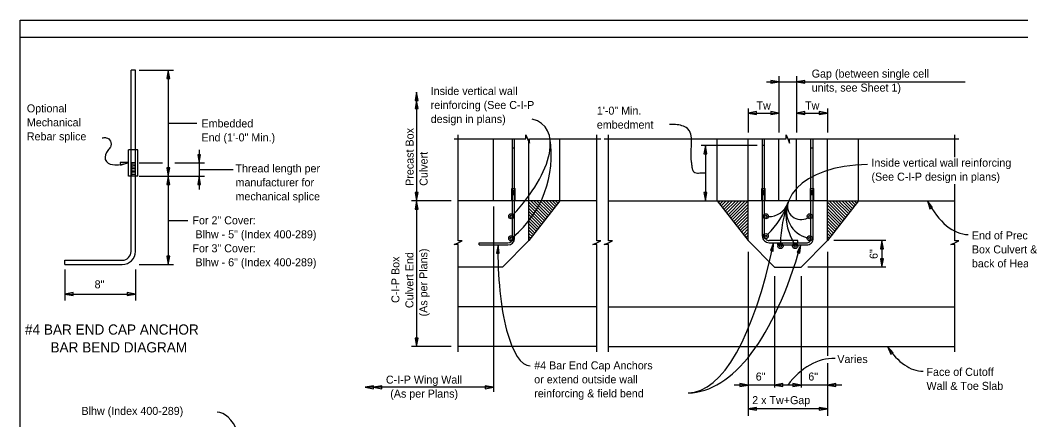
# Model space of a CAD drawing. Extents: x 0 to 30.8, y 0 to 19.8.
# Drawn here: x 0 to 18.91, y 12.25 to 19.8 of the extents above; entities that cross this region are included whole.
import ezdxf

# ---------------------------------------------------------------- set-up
doc = ezdxf.new("R2010")
doc.units = 0
for name, color, linetype in [('Dimension', 7, 'Continuous'), ('Leader', 7, 'Continuous'), ('Miscellaneous', 7, 'Continuous'), ('Miscellaneous1', 7, 'Continuous'), ('Rebar', 7, 'Continuous'), ('SubStrConc', 7, 'Continuous'), ('SubStrConc_h', 7, 'Continuous'), ('TextStructures', 7, 'Continuous')]:
    doc.layers.add(name, color=color, linetype=linetype)

msp = doc.modelspace()

# ---------------------------------------------------------------- linework, layer by layer
at = {"layer": 'Dimension'}
for p, q in [((2.253, 18.853), (2.902, 18.853)), ((2.8, 18.853), (2.8, 16.853)), ((14.335, 18.743), (14.335, 17.678)), ((14.668, 18.743), (14.668, 17.678)), ((14.098, 18.633), (14.335, 18.633)), ((14.335, 18.633), (14.668, 18.633)), ((14.668, 18.633), (17.851, 18.633)), ((7.491, 18.44), (7.491, 16.39)), ((13.751, 18.129), (13.751, 17.678)), ((13.751, 18.045), (14.335, 18.045)), ((14.668, 18.045), (15.251, 18.045)), ((15.251, 18.129), (15.251, 17.678)), ((2.8, 17.853), (3.337, 17.853)), ((17.656, 17.21), (17.656, 17.634)), ((13.922, 17.431), (12.868, 17.431)), ((12.944, 17.431), (12.944, 16.39)), ((3.383, 17.353), (3.383, 17.103)), ((2.253, 17.103), (2.688, 17.103)), ((2.923, 17.103), (3.483, 17.103)), ((3.383, 17.103), (3.383, 16.853)), ((2.253, 16.853), (3.483, 16.853)), ((2.8, 16.853), (2.8, 15.187)), ((3.383, 16.978), (4.023, 16.978)), ((3.383, 16.853), (3.383, 16.603)), ((8.145, 16.39), (7.393, 16.39)), ((7.491, 16.39), (7.491, 13.64)), ((8.945, 16.284), (8.945, 12.783)), ((2.8, 16.02), (3.172, 16.02)), ((16.351, 15.64), (15.374, 15.64)), ((16.28, 15.64), (16.28, 15.14)), ((13.751, 15.425), (13.751, 12.335)), ((15.251, 15.425), (15.251, 13.464)), ((2.253, 15.187), (2.902, 15.187)), ((16.351, 15.14), (14.882, 15.14)), ((0.847, 15.091), (0.847, 14.508)), ((2.18, 15.091), (2.18, 14.508)), ((14.251, 14.966), (14.251, 12.869)), ((14.751, 14.966), (14.751, 12.869)), ((0.847, 14.63), (2.18, 14.63)), ((8.145, 13.64), (7.393, 13.64)), ((15.251, 13.329), (15.251, 12.335)), ((8.943, 12.872), (6.52, 12.872)), ((13.751, 12.913), (13.488, 12.913)), ((14.251, 12.913), (13.751, 12.913)), ((14.751, 12.913), (14.251, 12.913)), ((15.251, 12.913), (14.751, 12.913)), ((15.525, 12.913), (15.251, 12.913)), ((15.251, 12.465), (13.751, 12.465))]:
    msp.add_line(p, q, dxfattribs=at)
for points in [[(2.8, 18.853), (2.774, 18.697), (2.827, 18.697)], [(14.335, 18.633), (14.179, 18.66), (14.179, 18.607)], [(14.668, 18.633), (14.824, 18.607), (14.824, 18.66)], [(7.491, 18.44), (7.465, 18.284), (7.517, 18.284)], [(7.491, 18.284), (7.465, 18.128), (7.517, 18.128)], [(13.751, 18.045), (13.908, 18.019), (13.908, 18.072)], [(14.335, 18.045), (14.179, 18.072), (14.179, 18.019)], [(14.668, 18.045), (14.824, 18.019), (14.824, 18.072)], [(15.251, 18.045), (15.095, 18.072), (15.095, 18.019)], [(12.944, 17.431), (12.918, 17.275), (12.971, 17.275)], [(3.383, 17.103), (3.409, 17.26), (3.356, 17.26)], [(2.05, 17.11), (1.892, 17.111), (1.9, 17.059)], [(2.8, 16.853), (2.827, 17.01), (2.774, 17.01)], [(2.8, 16.853), (2.774, 16.697), (2.827, 16.697)], [(3.383, 16.853), (3.356, 16.697), (3.409, 16.697)], [(7.491, 16.39), (7.517, 16.546), (7.465, 16.546)], [(12.944, 16.39), (12.971, 16.546), (12.918, 16.546)], [(7.491, 16.39), (7.465, 16.233), (7.517, 16.233)], [(17.137, 16.39), (17.187, 16.239), (17.234, 16.264)], [(9.029, 15.556), (9, 15.401), (9.053, 15.4)], [(14.234, 15.598), (14.176, 15.45), (14.228, 15.44)], [(14.747, 15.556), (14.679, 15.413), (14.73, 15.399)], [(16.28, 15.64), (16.253, 15.483), (16.306, 15.483)], [(2.8, 15.187), (2.827, 15.343), (2.774, 15.343)], [(16.28, 15.14), (16.306, 15.296), (16.253, 15.296)], [(0.847, 14.63), (1.003, 14.604), (1.003, 14.657)], [(2.18, 14.63), (2.024, 14.657), (2.024, 14.604)], [(7.491, 13.64), (7.517, 13.796), (7.465, 13.796)], [(16.384, 13.64), (16.448, 13.495), (16.492, 13.524)], [(6.52, 12.872), (6.676, 12.845), (6.676, 12.898)], [(6.676, 12.872), (6.832, 12.845), (6.832, 12.898)], [(8.943, 12.872), (8.787, 12.898), (8.787, 12.845)], [(13.751, 12.913), (13.595, 12.94), (13.595, 12.887)], [(14.251, 12.913), (14.408, 12.887), (14.408, 12.94)], [(14.751, 12.913), (14.595, 12.94), (14.595, 12.887)], [(15.251, 12.913), (15.408, 12.887), (15.408, 12.94)], [(13.751, 12.465), (13.908, 12.438), (13.908, 12.491)], [(15.251, 12.465), (15.095, 12.491), (15.095, 12.438)]]:
    msp.add_lwpolyline(points, close=True, dxfattribs=at)
for points in [[(8.276, 13.54), (8.276, 15.564), (8.198, 15.564), (8.276, 15.598), (8.353, 15.632), (8.276, 15.632), (8.276, 17.634)], [(8.198, 17.556), (9.552, 17.556), (9.552, 17.634), (9.586, 17.556), (9.62, 17.479), (9.62, 17.556), (10.973, 17.556)], [(10.896, 13.54), (10.896, 15.564), (10.818, 15.564), (10.896, 15.598), (10.973, 15.632), (10.896, 15.632), (10.896, 17.634)], [(11.035, 17.556), (14.468, 17.556), (14.468, 17.634), (14.501, 17.556), (14.535, 17.479), (14.535, 17.556), (17.734, 17.556)], [(11.112, 13.54), (11.112, 15.564), (11.035, 15.564), (11.112, 15.598), (11.19, 15.632), (11.112, 15.632), (11.112, 17.634)], [(17.656, 13.54), (17.656, 15.564), (17.579, 15.564), (17.656, 15.598), (17.734, 15.632), (17.656, 15.632), (17.656, 16.703)]]:
    msp.add_lwpolyline(points, dxfattribs=at)
for centre in [(9.278, 16.098), (14.085, 16.098), (14.918, 16.098), (9.278, 15.681), (14.085, 15.723), (14.918, 15.681), (14.363, 15.535), (14.64, 15.535)]:
    msp.add_circle(centre, 0.0484, dxfattribs=at)
for centre, radius, start, end in [((8.021, 17.252), 2.014, 310.0351, 9.0815), ((13.082, 16.845), 1.505, 313.6067, 341.4608), ((14.145, 16.47), 0.377, 268.0838, 340.54), ((16.782, 15.537), 2.42, 159.9499, 178.8939), ((14.997, 16.193), 0.518, 159.2154, 255.8414), ((14.75, 16.287), 0.253, 159.2154, 300.6523)]:
    msp.add_arc(centre, radius, start, end, dxfattribs=at)
for centre, major_axis, ratio, start_param, end_param in [((8.516, 16.534), (-1.388, -1.268), 0.452293, 1.740338, 3.438697), ((17.353, 15.385), (2.849, -0.969), 0.486344, 2.219026, 3.635956), ((17.955, 18.642), (0.044, 2.889), 0.436833, 2.471547, 3.141593), ((9.65, 15.479), (0.017, 2.202), 0.282679, 1.537886, 3.141593), ((12.497, 20.209), (-0.124, 7.444), 0.285208, 3.141593, 4.03961), ((12.497, 20.209), (-0.124, 7.444), 0.375791, 3.141593, 4.03097), ((17.101, 16.062), (0.044, 2.889), 0.436833, 2.572127, 3.141593), ((15.347, 11.482), (-0.047, -1.933), 0.665458, 3.141593, 3.895381), ((3.768, 10.977), (0.045, -1.424), 0.393454, 2.379989, 3.141593)]:
    msp.add_ellipse(centre, major_axis=major_axis, ratio=ratio, start_param=start_param, end_param=end_param, dxfattribs=at)
msp.add_spline([(12.944, 16.91), (12.861, 16.91), (12.773, 16.91), (12.726, 16.932), (12.706, 16.977), (12.7, 16.998), (12.694, 17.032), (12.688, 17.1), (12.682, 17.136), (12.675, 17.198), (12.605, 17.755), (12.38, 17.827), (12.268, 17.827)], degree=3, dxfattribs=at)
at = {"layer": 'Leader'}
msp.add_spline([(1.554, 17.578), (1.63, 17.578), (1.707, 17.517), (1.707, 17.402), (1.661, 17.341), (1.611, 17.169), (1.632, 17.129), (1.79, 17.068), (2.05, 17.11)], degree=3, dxfattribs=at)
at = {"layer": 'Miscellaneous'}
for p, q in [((9.289, 16.389), (9.289, 16.619)), ((9.299, 16.546), (9.299, 16.586)), ((9.299, 16.586), (9.341, 16.586)), ((9.299, 16.576), (9.341, 16.576)), ((9.299, 16.566), (9.341, 16.566)), ((9.299, 16.556), (9.341, 16.556)), ((9.299, 16.506), (9.299, 16.546)), ((9.299, 16.546), (9.341, 16.546)), ((9.299, 16.536), (9.341, 16.536)), ((9.299, 16.526), (9.341, 16.526)), ((9.299, 16.516), (9.341, 16.516)), ((9.299, 16.506), (9.341, 16.506)), ((9.341, 16.546), (9.341, 16.586)), ((9.341, 16.506), (9.341, 16.546)), ((9.351, 16.389), (9.351, 16.619)), ((14.012, 16.389), (14.012, 16.619)), ((14.022, 16.546), (14.022, 16.586)), ((14.022, 16.586), (14.064, 16.586)), ((14.022, 16.576), (14.064, 16.576)), ((14.022, 16.566), (14.064, 16.566)), ((14.022, 16.556), (14.064, 16.556)), ((14.022, 16.506), (14.022, 16.546)), ((14.022, 16.546), (14.064, 16.546)), ((14.022, 16.536), (14.064, 16.536)), ((14.022, 16.526), (14.064, 16.526)), ((14.022, 16.516), (14.064, 16.516)), ((14.022, 16.506), (14.064, 16.506)), ((14.064, 16.546), (14.064, 16.586)), ((14.064, 16.506), (14.064, 16.546)), ((14.074, 16.389), (14.074, 16.619)), ((14.929, 16.389), (14.929, 16.619)), ((14.939, 16.546), (14.939, 16.586)), ((14.939, 16.586), (14.981, 16.586)), ((14.939, 16.576), (14.981, 16.576)), ((14.939, 16.566), (14.981, 16.566)), ((14.939, 16.556), (14.981, 16.556)), ((14.939, 16.506), (14.939, 16.546)), ((14.939, 16.546), (14.981, 16.546)), ((14.939, 16.536), (14.981, 16.536)), ((14.939, 16.526), (14.981, 16.526)), ((14.939, 16.516), (14.981, 16.516)), ((14.939, 16.506), (14.981, 16.506)), ((14.981, 16.546), (14.981, 16.586)), ((14.981, 16.506), (14.981, 16.546)), ((14.991, 16.389), (14.991, 16.619))]:
    msp.add_line(p, q, dxfattribs=at)
for points in [[(9.289, 16.619), (9.351, 16.619)], [(14.012, 16.619), (14.074, 16.619)], [(14.929, 16.619), (14.991, 16.619)]]:
    msp.add_lwpolyline(points, dxfattribs=at)
at = {"layer": 'Miscellaneous1'}
msp.add_lwpolyline([(0, 19.8), (30.8, 19.8), (30.8, 0), (0, 0)], close=True, dxfattribs=at)
at = {"layer": 'Rebar'}
for p, q in [((2.097, 16.853), (2.097, 18.853)), ((2.18, 18.853), (2.097, 18.853)), ((2.18, 16.853), (2.18, 18.853)), ((9.299, 17.39), (9.299, 17.556)), ((9.341, 17.39), (9.341, 17.556)), ((14.022, 17.39), (14.022, 17.556)), ((14.022, 15.723), (14.022, 17.431)), ((14.064, 17.431), (14.022, 17.431)), ((14.064, 17.39), (14.064, 17.556)), ((14.064, 15.723), (14.064, 17.431)), ((14.939, 17.39), (14.939, 17.556)), ((14.981, 17.39), (14.981, 17.556)), ((2.05, 16.853), (2.05, 17.353)), ((2.227, 17.353), (2.05, 17.353)), ((2.227, 16.853), (2.227, 17.353)), ((9.299, 15.681), (9.299, 17.39)), ((9.299, 17.39), (9.341, 17.39)), ((9.341, 15.681), (9.341, 17.39)), ((14.939, 15.681), (14.939, 17.39)), ((14.939, 17.39), (14.981, 17.39)), ((14.981, 15.681), (14.981, 17.39)), ((2.117, 17.103), (2.097, 17.102)), ((2.1, 17.103), (2.097, 17.102)), ((2.097, 17.102), (2.111, 17.096)), ((2.111, 17.096), (2.097, 17.088)), ((2.097, 17.088), (2.111, 17.082)), ((2.111, 17.082), (2.097, 17.074)), ((2.181, 17.081), (2.097, 17.074)), ((2.097, 17.074), (2.111, 17.068)), ((2.111, 17.068), (2.097, 17.06)), ((2.097, 17.06), (2.111, 17.054)), ((2.111, 17.054), (2.097, 17.046)), ((2.181, 17.053), (2.097, 17.046)), ((2.097, 17.046), (2.111, 17.04)), ((2.111, 17.04), (2.097, 17.032)), ((2.097, 17.032), (2.111, 17.027)), ((2.111, 17.027), (2.097, 17.018)), ((2.181, 17.026), (2.097, 17.018)), ((2.097, 17.018), (2.111, 17.013)), ((2.171, 17.103), (2.1, 17.103)), ((2.171, 17.103), (2.167, 17.101)), ((2.167, 17.101), (2.181, 17.095)), ((2.181, 17.095), (2.167, 17.087)), ((2.167, 17.087), (2.181, 17.081)), ((2.181, 17.081), (2.167, 17.073)), ((2.167, 17.073), (2.181, 17.067)), ((2.181, 17.067), (2.167, 17.059)), ((2.167, 17.059), (2.181, 17.053)), ((2.181, 17.053), (2.167, 17.045)), ((2.167, 17.045), (2.181, 17.04)), ((2.181, 17.04), (2.167, 17.031)), ((2.167, 17.031), (2.181, 17.026)), ((2.181, 17.026), (2.167, 17.018)), ((2.167, 17.018), (2.181, 17.012)), ((2.227, 16.853), (2.05, 16.853)), ((2.111, 17.013), (2.097, 17.005)), ((2.097, 17.005), (2.111, 16.999)), ((2.111, 16.999), (2.097, 16.991)), ((2.181, 16.998), (2.097, 16.991)), ((2.097, 16.991), (2.111, 16.985)), ((2.111, 16.985), (2.097, 16.977)), ((2.097, 16.977), (2.111, 16.971)), ((2.111, 16.971), (2.097, 16.963)), ((2.181, 16.97), (2.097, 16.963)), ((2.097, 16.963), (2.111, 16.957)), ((2.111, 16.957), (2.097, 16.949)), ((2.097, 16.949), (2.111, 16.943)), ((2.181, 16.943), (2.097, 16.935)), ((2.111, 16.943), (2.097, 16.935)), ((2.097, 16.935), (2.111, 16.93)), ((2.111, 16.93), (2.097, 16.921)), ((2.097, 16.921), (2.111, 16.916)), ((2.111, 16.916), (2.097, 16.908)), ((2.181, 16.915), (2.097, 16.908)), ((2.097, 16.908), (2.111, 16.902)), ((2.111, 16.902), (2.097, 16.894)), ((2.097, 16.894), (2.111, 16.888)), ((2.111, 16.888), (2.097, 16.88)), ((2.181, 16.887), (2.097, 16.88)), ((2.097, 16.88), (2.111, 16.874)), ((2.111, 16.874), (2.097, 16.866)), ((2.097, 16.866), (2.111, 16.86)), ((2.097, 15.436), (2.097, 16.853)), ((2.18, 16.853), (2.097, 16.853)), ((2.111, 16.86), (2.099, 16.853)), ((2.181, 16.859), (2.11, 16.853)), ((2.181, 17.012), (2.167, 17.004)), ((2.167, 17.004), (2.181, 16.998)), ((2.181, 16.998), (2.167, 16.99)), ((2.167, 16.99), (2.181, 16.984)), ((2.181, 16.984), (2.167, 16.976)), ((2.167, 16.976), (2.181, 16.97)), ((2.181, 16.97), (2.167, 16.962)), ((2.167, 16.962), (2.181, 16.956)), ((2.181, 16.956), (2.167, 16.948)), ((2.167, 16.948), (2.181, 16.943)), ((2.181, 16.943), (2.167, 16.935)), ((2.167, 16.935), (2.181, 16.929)), ((2.181, 16.929), (2.167, 16.921)), ((2.167, 16.921), (2.181, 16.915)), ((2.181, 16.915), (2.167, 16.907)), ((2.167, 16.907), (2.181, 16.901)), ((2.181, 16.901), (2.167, 16.893)), ((2.167, 16.893), (2.181, 16.887)), ((2.181, 16.887), (2.167, 16.879)), ((2.167, 16.879), (2.181, 16.873)), ((2.181, 16.873), (2.167, 16.865)), ((2.167, 16.865), (2.181, 16.859)), ((2.181, 16.859), (2.17, 16.853)), ((2.18, 15.436), (2.18, 16.853)), ((8.674, 15.556), (8.674, 15.598)), ((8.674, 15.598), (9.216, 15.598)), ((8.674, 15.556), (9.216, 15.556)), ((14.689, 15.639), (14.147, 15.639)), ((14.147, 15.598), (14.856, 15.598)), ((14.314, 15.556), (14.314, 15.598)), ((14.314, 15.556), (14.856, 15.556)), ((14.689, 15.598), (14.689, 15.639)), ((0.847, 15.187), (0.847, 15.27)), ((0.847, 15.27), (1.931, 15.27)), ((0.847, 15.187), (1.931, 15.187))]:
    msp.add_line(p, q, dxfattribs=at)
for centre in [(9.278, 16.098), (14.085, 16.098), (14.918, 16.098), (9.278, 15.681), (14.085, 15.723), (14.918, 15.681), (14.363, 15.535), (14.64, 15.535)]:
    msp.add_circle(centre, 0.0208, dxfattribs=at)
for centre, radius, start, end in [((14.147, 15.723), 0.125, 179.9945, 269.9955), ((14.147, 15.723), 0.0833, 179.996, 270), ((9.216, 15.681), 0.0833, 270.002, 0.0007), ((9.216, 15.681), 0.125, 270.0048, 0.0009), ((14.856, 15.681), 0.0833, 270, 0.0007), ((14.856, 15.681), 0.125, 270, 0.0009), ((1.931, 15.436), 0.167, 270.002, 0.0007), ((1.931, 15.436), 0.25, 270.0048, 0.0009)]:
    msp.add_arc(centre, radius, start, end, dxfattribs=at)
at = {"layer": 'SubStrConc'}
for p, q in [((9.611, 15.64), (9.611, 16.39)), ((10.195, 16.39), (9.611, 15.64)), ((9.611, 16.364), (9.928, 16.047)), ((9.611, 16.305), (9.903, 16.014)), ((9.645, 16.39), (9.954, 16.08)), ((9.704, 16.39), (9.98, 16.114)), ((9.763, 16.39), (10.006, 16.147)), ((9.822, 16.39), (10.032, 16.18)), ((9.881, 16.39), (10.057, 16.213)), ((9.94, 16.39), (10.083, 16.246)), ((9.999, 16.39), (10.109, 16.279)), ((10.058, 16.39), (10.135, 16.312)), ((10.117, 16.39), (10.161, 16.346)), ((10.175, 16.39), (10.186, 16.379)), ((13.168, 16.39), (13.751, 15.64)), ((13.192, 16.359), (13.222, 16.39)), ((13.218, 16.326), (13.281, 16.39)), ((13.243, 16.293), (13.34, 16.39)), ((13.269, 16.26), (13.399, 16.39)), ((13.295, 16.226), (13.458, 16.39)), ((13.321, 16.193), (13.517, 16.39)), ((13.347, 16.16), (13.576, 16.39)), ((13.372, 16.127), (13.635, 16.39)), ((13.398, 16.094), (13.694, 16.39)), ((13.424, 16.061), (13.751, 16.388)), ((13.45, 16.028), (13.751, 16.329)), ((13.475, 15.994), (13.751, 16.27)), ((13.751, 15.64), (13.751, 16.39)), ((15.251, 16.39), (13.751, 16.39)), ((15.251, 15.64), (15.251, 16.39)), ((15.835, 16.39), (15.251, 15.64)), ((15.251, 16.364), (15.568, 16.047)), ((15.251, 16.305), (15.543, 16.014)), ((15.285, 16.39), (15.594, 16.08)), ((15.344, 16.39), (15.62, 16.114)), ((15.403, 16.39), (15.646, 16.147)), ((15.462, 16.39), (15.672, 16.18)), ((15.521, 16.39), (15.697, 16.213)), ((15.58, 16.39), (15.723, 16.246)), ((15.639, 16.39), (15.749, 16.279)), ((15.698, 16.39), (15.775, 16.312)), ((15.757, 16.39), (15.8, 16.346)), ((15.815, 16.39), (15.826, 16.379)), ((9.611, 16.247), (9.877, 15.981)), ((9.611, 16.188), (9.851, 15.948)), ((9.611, 16.129), (9.825, 15.915)), ((13.501, 15.961), (13.751, 16.212)), ((13.527, 15.928), (13.751, 16.153)), ((13.553, 15.895), (13.751, 16.094)), ((15.251, 16.247), (15.517, 15.981)), ((15.251, 16.188), (15.491, 15.948)), ((15.251, 16.129), (15.465, 15.915)), ((9.611, 16.07), (9.8, 15.882)), ((9.611, 16.011), (9.774, 15.848)), ((9.611, 15.952), (9.748, 15.815)), ((9.611, 15.893), (9.722, 15.782)), ((13.579, 15.862), (13.751, 16.035)), ((13.604, 15.829), (13.751, 15.976)), ((13.63, 15.796), (13.751, 15.917)), ((15.251, 16.07), (15.44, 15.882)), ((15.251, 16.011), (15.414, 15.848)), ((15.251, 15.952), (15.388, 15.815)), ((15.251, 15.893), (15.362, 15.782)), ((9.611, 15.834), (9.696, 15.749)), ((9.611, 15.775), (9.671, 15.716)), ((9.611, 15.716), (9.645, 15.683)), ((13.656, 15.762), (13.751, 15.858)), ((13.682, 15.729), (13.751, 15.799)), ((13.707, 15.696), (13.751, 15.74)), ((15.251, 15.834), (15.336, 15.749)), ((15.251, 15.775), (15.311, 15.716)), ((15.251, 15.716), (15.285, 15.683)), ((9.111, 15.14), (9.611, 15.64)), ((9.611, 15.657), (9.619, 15.65)), ((13.733, 15.663), (13.751, 15.681)), ((14.251, 15.14), (13.751, 15.64)), ((14.751, 15.14), (15.251, 15.64)), ((15.251, 15.657), (15.259, 15.65)), ((9.111, 15.14), (8.276, 15.14)), ((14.251, 15.14), (14.751, 15.14)), ((14.251, 15.14), (14.751, 15.14)), ((10.896, 13.64), (8.276, 13.64)), ((11.112, 13.64), (17.656, 13.64))]:
    msp.add_line(p, q, dxfattribs=at)
at = {"layer": 'SubStrConc_h'}
for p, q in [((8.945, 16.39), (8.945, 17.556)), ((9.611, 16.39), (9.611, 17.556)), ((10.195, 16.39), (10.195, 17.556)), ((13.168, 16.39), (13.168, 17.556)), ((13.751, 16.39), (13.751, 17.556)), ((14.335, 16.39), (14.335, 17.556)), ((14.668, 16.39), (14.668, 17.556)), ((15.251, 16.39), (15.251, 17.556)), ((15.835, 16.39), (15.835, 17.556)), ((10.896, 16.39), (8.276, 16.39)), ((11.112, 16.39), (13.751, 16.39)), ((15.251, 16.39), (17.656, 16.39)), ((10.896, 14.39), (8.276, 14.39)), ((11.112, 14.39), (17.656, 14.39))]:
    msp.add_line(p, q, dxfattribs=at)
at = {"layer": 'TextStructures'}
msp.add_lwpolyline([(0, 19.477), (30.8, 19.477), (30.8, 0), (0, 0)], close=True, dxfattribs=at)

# ---------------------------------------------------------------- texts
at = {"layer": 'Dimension'}
for s, height, p in [('Gap (between single cell', 0.1512, (14.953, 18.714)), ('Inside vertical wall', 0.1512, (7.757, 18.386)), ('units, see Sheet 1)', 0.1512, (14.953, 18.45)), ('Optional', 0.1512, (0.129, 18.058)), ('reinforcing (See C-I-P', 0.1512, (7.757, 18.122)), ('1\'-0" Min.', 0.1512, (10.895, 18.015)), ('design in plans)', 0.1512, (7.757, 17.858)), ('Mechanical', 0.1512, (0.129, 17.794)), ('Embedded', 0.1512, (3.427, 17.774)), ('embedment', 0.1512, (10.895, 17.751)), ('Rebar splice', 0.1512, (0.129, 17.53)), ('End (1\'-0" Min.)', 0.1512, (3.427, 17.51)), ('Thread length per', 0.1512, (4.07, 16.926)), ('Inside vertical wall reinforcing', 0.1512, (16.082, 17.033)), ('(See C-I-P design in plans)', 0.1512, (16.082, 16.769)), ('manufacturer for', 0.1512, (4.07, 16.662)), ('mechanical splice', 0.1512, (4.07, 16.398)), ('For 2" Cover:', 0.1512, (3.257, 15.946)), (' Blhw - 5" (Index 400-289)', 0.1512, (3.257, 15.682)), ('End of Precast', 0.1512, (17.978, 15.661)), ('For 3" Cover:', 0.1512, (3.257, 15.418)), ('Box Culvert &', 0.1512, (17.978, 15.397)), (' Blhw - 6" (Index 400-289)', 0.1512, (3.257, 15.154)), ('back of Headwall', 0.1512, (17.978, 15.133)), ('#4 BAR END CAP ANCHOR', 0.192, (0.094, 13.865)), ('BAR BEND DIAGRAM', 0.192, (0.575, 13.529)), ('#4 Bar End Cap Anchors', 0.1512, (9.712, 13.209)), ('Face of Cutoff', 0.1512, (17.121, 13.086)), ('C-I-P Wing Wall', 0.1512, (6.911, 12.94)), ('or extend outside wall', 0.1512, (9.712, 12.945)), ('Wall & Toe Slab', 0.1512, (17.121, 12.822)), ('(As per Plans)', 0.1512, (6.993, 12.676)), ('reinforcing & field bend', 0.1512, (9.712, 12.681)), ('Blhw (Index 400-289)', 0.1512, (1.161, 12.35))]:
    msp.add_text(s, height=height, dxfattribs=at).set_placement(p)
for s, p in [('Precast Box', (7.434, 16.672)), ('Culvert', (7.698, 16.672)), ('C-I-P Box', (7.166, 14.462)), ('Culvert End', (7.43, 14.365)), ('(As per Plans)', (7.694, 14.208))]:
    msp.add_text(s, height=0.1512, rotation=90, dxfattribs=at).set_placement(p)
at = {"layer": 'TextStructures'}
for s, p in [('Tw', (13.911, 18.112)), ('Tw', (14.828, 18.112)), ('8"', (1.409, 14.738)), ('Varies', (15.437, 13.328)), ('6"', (13.896, 12.998)), ('6"', (14.889, 12.998)), ('2 x Tw+Gap', (13.829, 12.553))]:
    msp.add_text(s, height=0.1512, dxfattribs=at).set_placement(p)
msp.add_text('6"', height=0.1512, rotation=90, dxfattribs=at).set_placement((16.199, 15.292))

doc.saveas('drawing.dxf')
